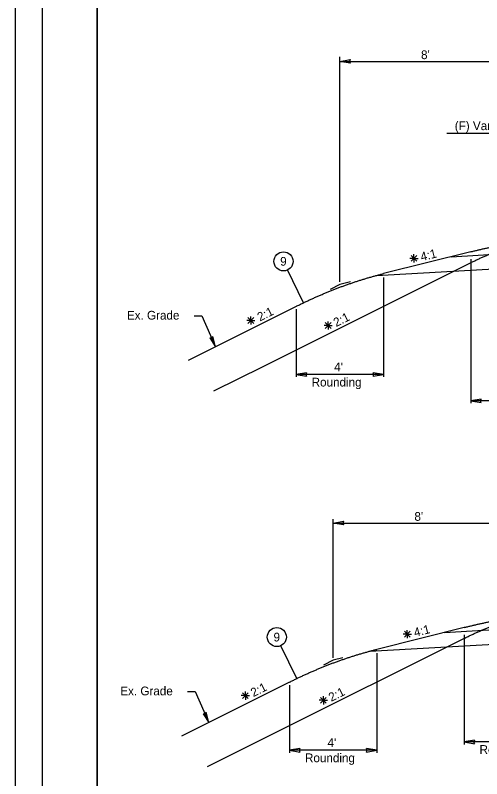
# Model space of a CAD drawing. Extents: x -219 to 803, y -225 to 180.
# Drawn here: x 0 to 42.8, y 20.4 to 90.4 of the extents above; entities that cross this region are included whole.
import ezdxf

# ---------------------------------------------------------------- set-up
doc = ezdxf.new("R2010")
doc.units = 0
for name, color, linetype in [('Level 16', 7, 'Continuous'), ('SH_Border', 7, 'Continuous'), ('XS_X_Pavt', 7, 'Continuous')]:
    doc.layers.add(name, color=color, linetype=linetype)

msp = doc.modelspace()

# ---------------------------------------------------------------- linework, layer by layer
at = {"layer": 'Level 16'}
for p, q in [((29.75, 65.913), (29.75, 86.556)), ((29.75, 86.128), (30.696, 86.286)), ((30.7, 85.97), (29.75, 86.128)), ((29.75, 86.128), (45.75, 86.128)), ((30.696, 86.286), (30.696, 86.286)), ((51.75, 79.528), (39.562, 79.528)), ((41.75, 68.678), (33.75, 66.678)), ((39.957, 68.23), (49.75, 68.778)), ((36.549, 68.073), (36.174, 68.073)), ((36.549, 68.073), (36.283, 68.338)), ((36.549, 68.073), (36.283, 67.808)), ((36.549, 68.073), (36.549, 68.448)), ((36.549, 68.073), (36.814, 68.338)), ((36.549, 68.073), (36.924, 68.073)), ((36.549, 68.073), (36.814, 67.808)), ((36.549, 68.073), (36.549, 67.698)), ((41.75, 67.996), (41.75, 54.797)), ((41.75, 67.678), (22.698, 58.152)), ((33.106, 66.51), (50.75, 67.499)), ((26.41, 64.001), (24.966, 67.014)), ((30.719, 65.92), (29.75, 65.678)), ((33.75, 66.323), (33.75, 57.21)), ((29.75, 65.678), (28.866, 65.236)), ((25.75, 63.678), (20.363, 60.985)), ((25.75, 63.41), (25.75, 57.21)), ((16.387, 62.802), (17.111, 62.802)), ((17.111, 62.802), (18.354, 59.98)), ((21.595, 62.383), (21.22, 62.383)), ((21.595, 62.383), (21.329, 62.648)), ((21.595, 62.383), (21.329, 62.117)), ((21.595, 62.383), (21.595, 62.758)), ((21.595, 62.383), (21.86, 62.648)), ((21.595, 62.383), (21.97, 62.383)), ((21.595, 62.383), (21.86, 62.117)), ((21.595, 62.383), (21.595, 62.008)), ((28.684, 61.925), (28.684, 62.3)), ((28.684, 61.925), (28.309, 61.925)), ((28.684, 61.925), (28.419, 62.19)), ((28.684, 61.925), (28.419, 61.66)), ((28.684, 61.925), (28.949, 62.19)), ((28.684, 61.925), (29.059, 61.925)), ((28.684, 61.925), (28.949, 61.66)), ((28.684, 61.925), (28.684, 61.55)), ((20.363, 60.985), (15.848, 58.727)), ((18.354, 59.98), (18.114, 60.909)), ((18.114, 60.909), (18.114, 60.909)), ((17.824, 60.784), (18.354, 59.98)), ((22.698, 58.152), (18.184, 55.895)), ((26.7, 57.586), (25.75, 57.428)), ((25.75, 57.428), (26.697, 57.27)), ((33.75, 57.428), (25.75, 57.428)), ((32.8, 57.27), (33.75, 57.428)), ((33.75, 57.428), (32.803, 57.586)), ((32.803, 57.586), (32.803, 57.586)), ((26.697, 57.27), (26.697, 57.27)), ((42.7, 55.173), (41.75, 55.015)), ((41.75, 55.015), (42.697, 54.857)), ((49.75, 55.015), (41.75, 55.015)), ((42.697, 54.857), (42.697, 54.857)), ((29.141, 31.489), (29.141, 44.194)), ((29.141, 43.827), (30.087, 43.985)), ((30.09, 43.669), (29.141, 43.827)), ((29.141, 43.827), (45.141, 43.827)), ((30.087, 43.985), (30.087, 43.985)), ((39.347, 33.806), (49.141, 34.354)), ((41.141, 34.254), (33.141, 32.254)), ((35.94, 33.649), (35.565, 33.649)), ((35.94, 33.649), (35.674, 33.914)), ((35.94, 33.649), (35.674, 33.384)), ((35.94, 33.649), (35.94, 34.024)), ((35.94, 33.649), (36.205, 33.914)), ((35.94, 33.649), (36.315, 33.649)), ((35.94, 33.649), (36.205, 33.384)), ((35.94, 33.649), (35.94, 33.274)), ((41.141, 33.254), (23.705, 24.536)), ((32.497, 32.086), (50.141, 33.074)), ((41.141, 33.572), (41.141, 23.55)), ((25.801, 29.577), (24.357, 32.59)), ((33.141, 31.899), (33.141, 22.785)), ((29.141, 31.254), (28.257, 30.812)), ((30.023, 31.475), (29.141, 31.254)), ((25.141, 29.254), (19.754, 26.56)), ((25.141, 28.967), (25.141, 22.785)), ((15.778, 28.378), (16.502, 28.378)), ((16.502, 28.378), (17.745, 25.556)), ((21.098, 28.013), (20.723, 28.013)), ((21.098, 28.013), (20.833, 28.278)), ((21.098, 28.013), (20.833, 27.747)), ((21.098, 28.013), (21.098, 28.388)), ((21.098, 28.013), (21.363, 28.278)), ((21.098, 28.013), (21.473, 28.013)), ((21.098, 28.013), (21.363, 27.747)), ((21.098, 28.013), (21.098, 27.638)), ((28.243, 27.585), (27.868, 27.585)), ((28.243, 27.585), (27.978, 27.85)), ((28.243, 27.585), (27.978, 27.32)), ((28.243, 27.585), (28.243, 27.96)), ((28.243, 27.585), (28.508, 27.85)), ((28.243, 27.585), (28.618, 27.585)), ((28.243, 27.585), (28.508, 27.32)), ((28.243, 27.585), (28.243, 27.21)), ((19.754, 26.56), (15.239, 24.303)), ((17.214, 26.36), (17.745, 25.556)), ((17.745, 25.556), (17.505, 26.485)), ((17.505, 26.485), (17.505, 26.485)), ((23.705, 24.536), (17.6, 21.484)), ((42.091, 23.926), (41.141, 23.768)), ((26.091, 23.162), (25.141, 23.004)), ((33.141, 23.004), (32.194, 23.162)), ((32.194, 23.162), (32.194, 23.162)), ((41.141, 23.768), (42.088, 23.61)), ((49.141, 23.768), (41.141, 23.768)), ((42.088, 23.61), (42.088, 23.61)), ((25.141, 23.004), (26.088, 22.846)), ((33.141, 23.004), (25.141, 23.004)), ((26.088, 22.846), (26.088, 22.846)), ((32.191, 22.846), (33.141, 23.004))]:
    msp.add_line(p, q, dxfattribs=at)
for centre in [(24.588, 67.803), (23.979, 33.379)]:
    msp.add_circle(centre, 0.875, dxfattribs=at)
for centre, start, end in [((30.939, 86.13), 147.14123, 213.822), ((17.873, 61.067), 260.14385, 326.82462), ((26.939, 57.426), 146.178, 212.85877), ((32.561, 57.43), 326.178, 32.85877), ((42.939, 55.013), 146.178, 212.85877), ((30.329, 43.829), 147.14123, 213.822), ((17.264, 26.643), 260.14385, 326.82462), ((42.33, 23.766), 146.178, 212.85877), ((26.33, 23.002), 146.178, 212.85877), ((31.952, 23.006), 326.178, 32.85877)]:
    msp.add_arc(centre, 0.288, start, end, dxfattribs=at)
for points in [[(41.75, 68.678), (41.904, 68.716), (42.058, 68.754), (42.212, 68.791), (42.365, 68.828), (42.519, 68.865), (42.673, 68.901), (42.827, 68.936), (42.981, 68.971), (43.135, 69.006), (43.288, 69.04), (43.442, 69.074), (43.596, 69.108), (43.75, 69.14), (43.904, 69.173), (44.058, 69.205), (44.212, 69.237), (44.365, 69.268), (44.519, 69.298), (44.673, 69.329), (44.827, 69.358), (44.981, 69.388), (45.135, 69.417), (45.288, 69.445), (45.442, 69.473), (45.596, 69.501), (45.75, 69.528), (45.904, 69.555), (46.058, 69.581), (46.212, 69.607), (46.365, 69.632), (46.519, 69.657), (46.673, 69.682), (46.827, 69.706), (46.981, 69.729), (47.135, 69.752), (47.288, 69.775), (47.442, 69.797), (47.596, 69.819), (47.75, 69.84), (47.904, 69.861), (48.058, 69.882), (48.212, 69.902), (48.365, 69.922), (48.519, 69.941), (48.673, 69.959), (48.827, 69.978), (48.981, 69.995), (49.135, 70.013), (49.288, 70.03), (49.442, 70.046), (49.596, 70.062), (49.75, 70.078)], [(41.75, 67.678), (41.904, 67.754), (42.058, 67.829), (42.212, 67.903), (42.365, 67.976), (42.519, 68.048), (42.673, 68.118), (42.827, 68.187), (42.981, 68.255), (43.135, 68.322), (43.288, 68.388), (43.442, 68.453), (43.596, 68.516), (43.75, 68.578), (43.904, 68.639), (44.058, 68.699), (44.212, 68.757), (44.365, 68.815), (44.519, 68.871), (44.673, 68.926), (44.827, 68.98), (44.981, 69.032), (45.135, 69.084), (45.288, 69.134), (45.442, 69.183), (45.596, 69.231), (45.75, 69.278), (45.904, 69.324), (46.058, 69.368), (46.212, 69.411), (46.365, 69.453), (46.519, 69.494), (46.673, 69.534), (46.827, 69.572), (46.981, 69.609), (47.135, 69.645), (47.288, 69.68), (47.442, 69.714), (47.596, 69.747), (47.75, 69.778), (47.904, 69.808), (48.058, 69.837), (48.212, 69.865), (48.365, 69.892), (48.519, 69.917), (48.673, 69.941), (48.827, 69.964), (48.981, 69.986), (49.135, 70.007), (49.288, 70.026), (49.442, 70.045), (49.596, 70.062), (49.75, 70.078)], [(25.75, 63.678), (25.904, 63.755), (26.058, 63.83), (26.212, 63.905), (26.365, 63.98), (26.519, 64.053), (26.673, 64.126), (26.827, 64.198), (26.981, 64.27), (27.135, 64.34), (27.288, 64.41), (27.442, 64.479), (27.596, 64.548), (27.75, 64.615), (27.904, 64.682), (28.058, 64.749), (28.212, 64.814), (28.365, 64.879), (28.519, 64.943), (28.673, 65.006), (28.827, 65.068), (28.981, 65.13), (29.135, 65.191), (29.288, 65.252), (29.442, 65.311), (29.596, 65.37), (29.75, 65.428), (29.904, 65.485), (30.058, 65.542), (30.212, 65.598), (30.365, 65.653), (30.519, 65.707), (30.673, 65.761), (30.827, 65.814), (30.981, 65.866), (31.135, 65.917), (31.288, 65.968), (31.442, 66.018), (31.596, 66.067), (31.75, 66.115), (31.904, 66.163), (32.058, 66.21), (32.212, 66.256), (32.365, 66.302), (32.519, 66.347), (32.673, 66.391), (32.827, 66.434), (32.981, 66.476), (33.135, 66.518), (33.288, 66.559), (33.442, 66.6), (33.596, 66.639), (33.75, 66.678)], [(41.141, 34.254), (41.295, 34.292), (41.449, 34.33), (41.602, 34.367), (41.756, 34.404), (41.91, 34.441), (42.064, 34.477), (42.218, 34.512), (42.372, 34.547), (42.525, 34.582), (42.679, 34.616), (42.833, 34.65), (42.987, 34.683), (43.141, 34.716), (43.295, 34.749), (43.449, 34.781), (43.602, 34.812), (43.756, 34.844), (43.91, 34.874), (44.064, 34.905), (44.218, 34.934), (44.372, 34.964), (44.525, 34.993), (44.679, 35.021), (44.833, 35.049), (44.987, 35.077), (45.141, 35.104), (45.295, 35.131), (45.449, 35.157), (45.602, 35.183), (45.756, 35.208), (45.91, 35.233), (46.064, 35.257), (46.218, 35.281), (46.372, 35.305), (46.525, 35.328), (46.679, 35.351), (46.833, 35.373), (46.987, 35.395), (47.141, 35.416), (47.295, 35.437), (47.449, 35.458), (47.602, 35.478), (47.756, 35.497), (47.91, 35.517), (48.064, 35.535), (48.218, 35.554), (48.372, 35.571), (48.525, 35.589), (48.679, 35.606), (48.833, 35.622), (48.987, 35.638), (49.141, 35.654)], [(41.141, 33.254), (41.295, 33.33), (41.449, 33.405), (41.602, 33.479), (41.756, 33.552), (41.91, 33.624), (42.064, 33.694), (42.218, 33.763), (42.372, 33.831), (42.525, 33.898), (42.679, 33.964), (42.833, 34.028), (42.987, 34.092), (43.141, 34.154), (43.295, 34.215), (43.449, 34.275), (43.602, 34.333), (43.756, 34.391), (43.91, 34.447), (44.064, 34.502), (44.218, 34.556), (44.372, 34.608), (44.525, 34.66), (44.679, 34.71), (44.833, 34.759), (44.987, 34.807), (45.141, 34.854), (45.295, 34.899), (45.449, 34.944), (45.602, 34.987), (45.756, 35.029), (45.91, 35.07), (46.064, 35.109), (46.218, 35.148), (46.372, 35.185), (46.525, 35.221), (46.679, 35.256), (46.833, 35.29), (46.987, 35.323), (47.141, 35.354), (47.295, 35.384), (47.449, 35.413), (47.602, 35.441), (47.756, 35.467), (47.91, 35.493), (48.064, 35.517), (48.218, 35.54), (48.372, 35.562), (48.525, 35.583), (48.679, 35.602), (48.833, 35.621), (48.987, 35.638), (49.141, 35.654)], [(25.141, 29.254), (25.295, 29.33), (25.449, 29.406), (25.602, 29.481), (25.756, 29.556), (25.91, 29.629), (26.064, 29.702), (26.218, 29.774), (26.372, 29.846), (26.525, 29.916), (26.679, 29.986), (26.833, 30.055), (26.987, 30.124), (27.141, 30.191), (27.295, 30.258), (27.449, 30.325), (27.602, 30.39), (27.756, 30.455), (27.91, 30.519), (28.064, 30.582), (28.218, 30.644), (28.372, 30.706), (28.525, 30.767), (28.679, 30.827), (28.833, 30.887), (28.987, 30.946), (29.141, 31.004), (29.295, 31.061), (29.449, 31.118), (29.602, 31.174), (29.756, 31.229), (29.91, 31.283), (30.064, 31.337), (30.218, 31.39), (30.372, 31.442), (30.525, 31.493), (30.679, 31.544), (30.833, 31.594), (30.987, 31.643), (31.141, 31.691), (31.295, 31.739), (31.449, 31.786), (31.602, 31.832), (31.756, 31.878), (31.91, 31.923), (32.064, 31.967), (32.218, 32.01), (32.372, 32.052), (32.525, 32.094), (32.679, 32.135), (32.833, 32.175), (32.987, 32.215), (33.141, 32.254)]]:
    msp.add_spline(points, degree=3, dxfattribs=at)
at = {"layer": 'SH_Border'}
for points in [[(0, 0), (170, 0), (170, 110), (0, 110)], [(2.5, 107.5), (7.5, 107.5), (7.5, 2.5), (2.5, 2.5)], [(7.5, 107.5), (167.5, 107.5), (167.5, 2.5), (7.5, 2.5)]]:
    msp.add_lwpolyline(points, close=True, dxfattribs=at)
at = {"layer": 'XS_X_Pavt'}
for points in [[(29.755, 86.126), (29.752, 86.128)], [(29.757, 86.126), (29.753, 86.128)], [(18.35, 59.986), (18.353, 59.983)], [(18.35, 59.984), (18.353, 59.983)], [(25.755, 57.43), (25.753, 57.427)], [(25.757, 57.429), (25.753, 57.427)], [(33.743, 57.427), (33.747, 57.428)], [(33.745, 57.426), (33.747, 57.428)], [(41.755, 55.017), (41.753, 55.014)], [(41.757, 55.016), (41.753, 55.014)], [(29.146, 43.825), (29.143, 43.827)], [(29.148, 43.825), (29.144, 43.827)], [(17.741, 25.562), (17.744, 25.559)], [(17.741, 25.56), (17.744, 25.558)], [(41.146, 23.77), (41.144, 23.768)], [(41.148, 23.77), (41.144, 23.768)], [(25.146, 23.006), (25.144, 23.003)], [(25.148, 23.005), (25.144, 23.003)], [(33.134, 23.002), (33.138, 23.004)], [(33.136, 23.002), (33.138, 23.004)]]:
    msp.add_lwpolyline(points, dxfattribs=at)

# ---------------------------------------------------------------- texts
at = {"layer": 'Level 16'}
for s, p in [("8'", (37.199, 86.333)), ("(F) Var. 6.4' to 2.2'", (40.29, 79.828)), ('9', (24.285, 67.403)), ('Ex. Grade', (10.234, 62.466)), ("4'", (29.235, 57.736)), ('Rounding', (27.169, 56.336)), ("8'", (36.59, 44.032)), ('9', (23.676, 32.979)), ('Ex. Grade', (9.625, 28.042)), ("4'", (28.626, 23.312)), ('Rounding', (42.56, 22.676)), ('Rounding', (26.56, 21.912))]:
    msp.add_text(s, height=0.8, dxfattribs=at).set_placement(p)
for s, rotation, p in [('4:1', 14.03624, (37.254, 67.815)), ('2:1', 26.56505, (22.434, 62.29)), ('2:1', 26.56505, (29.411, 61.778)), ('4:1', 14.03624, (36.645, 33.391)), ('2:1', 26.56505, (21.825, 27.866)), ('2:1', 26.56505, (28.97, 27.438))]:
    msp.add_text(s, height=0.8, rotation=rotation, dxfattribs=at).set_placement(p)

doc.saveas('drawing.dxf')
